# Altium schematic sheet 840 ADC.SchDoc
size 566 x 398 mm; Organization: Toradex Solutions Inc.; Address1: 6415 Northwest Drive; Address2: Mississauga, ON, L4V 1X1; Address3: Canada
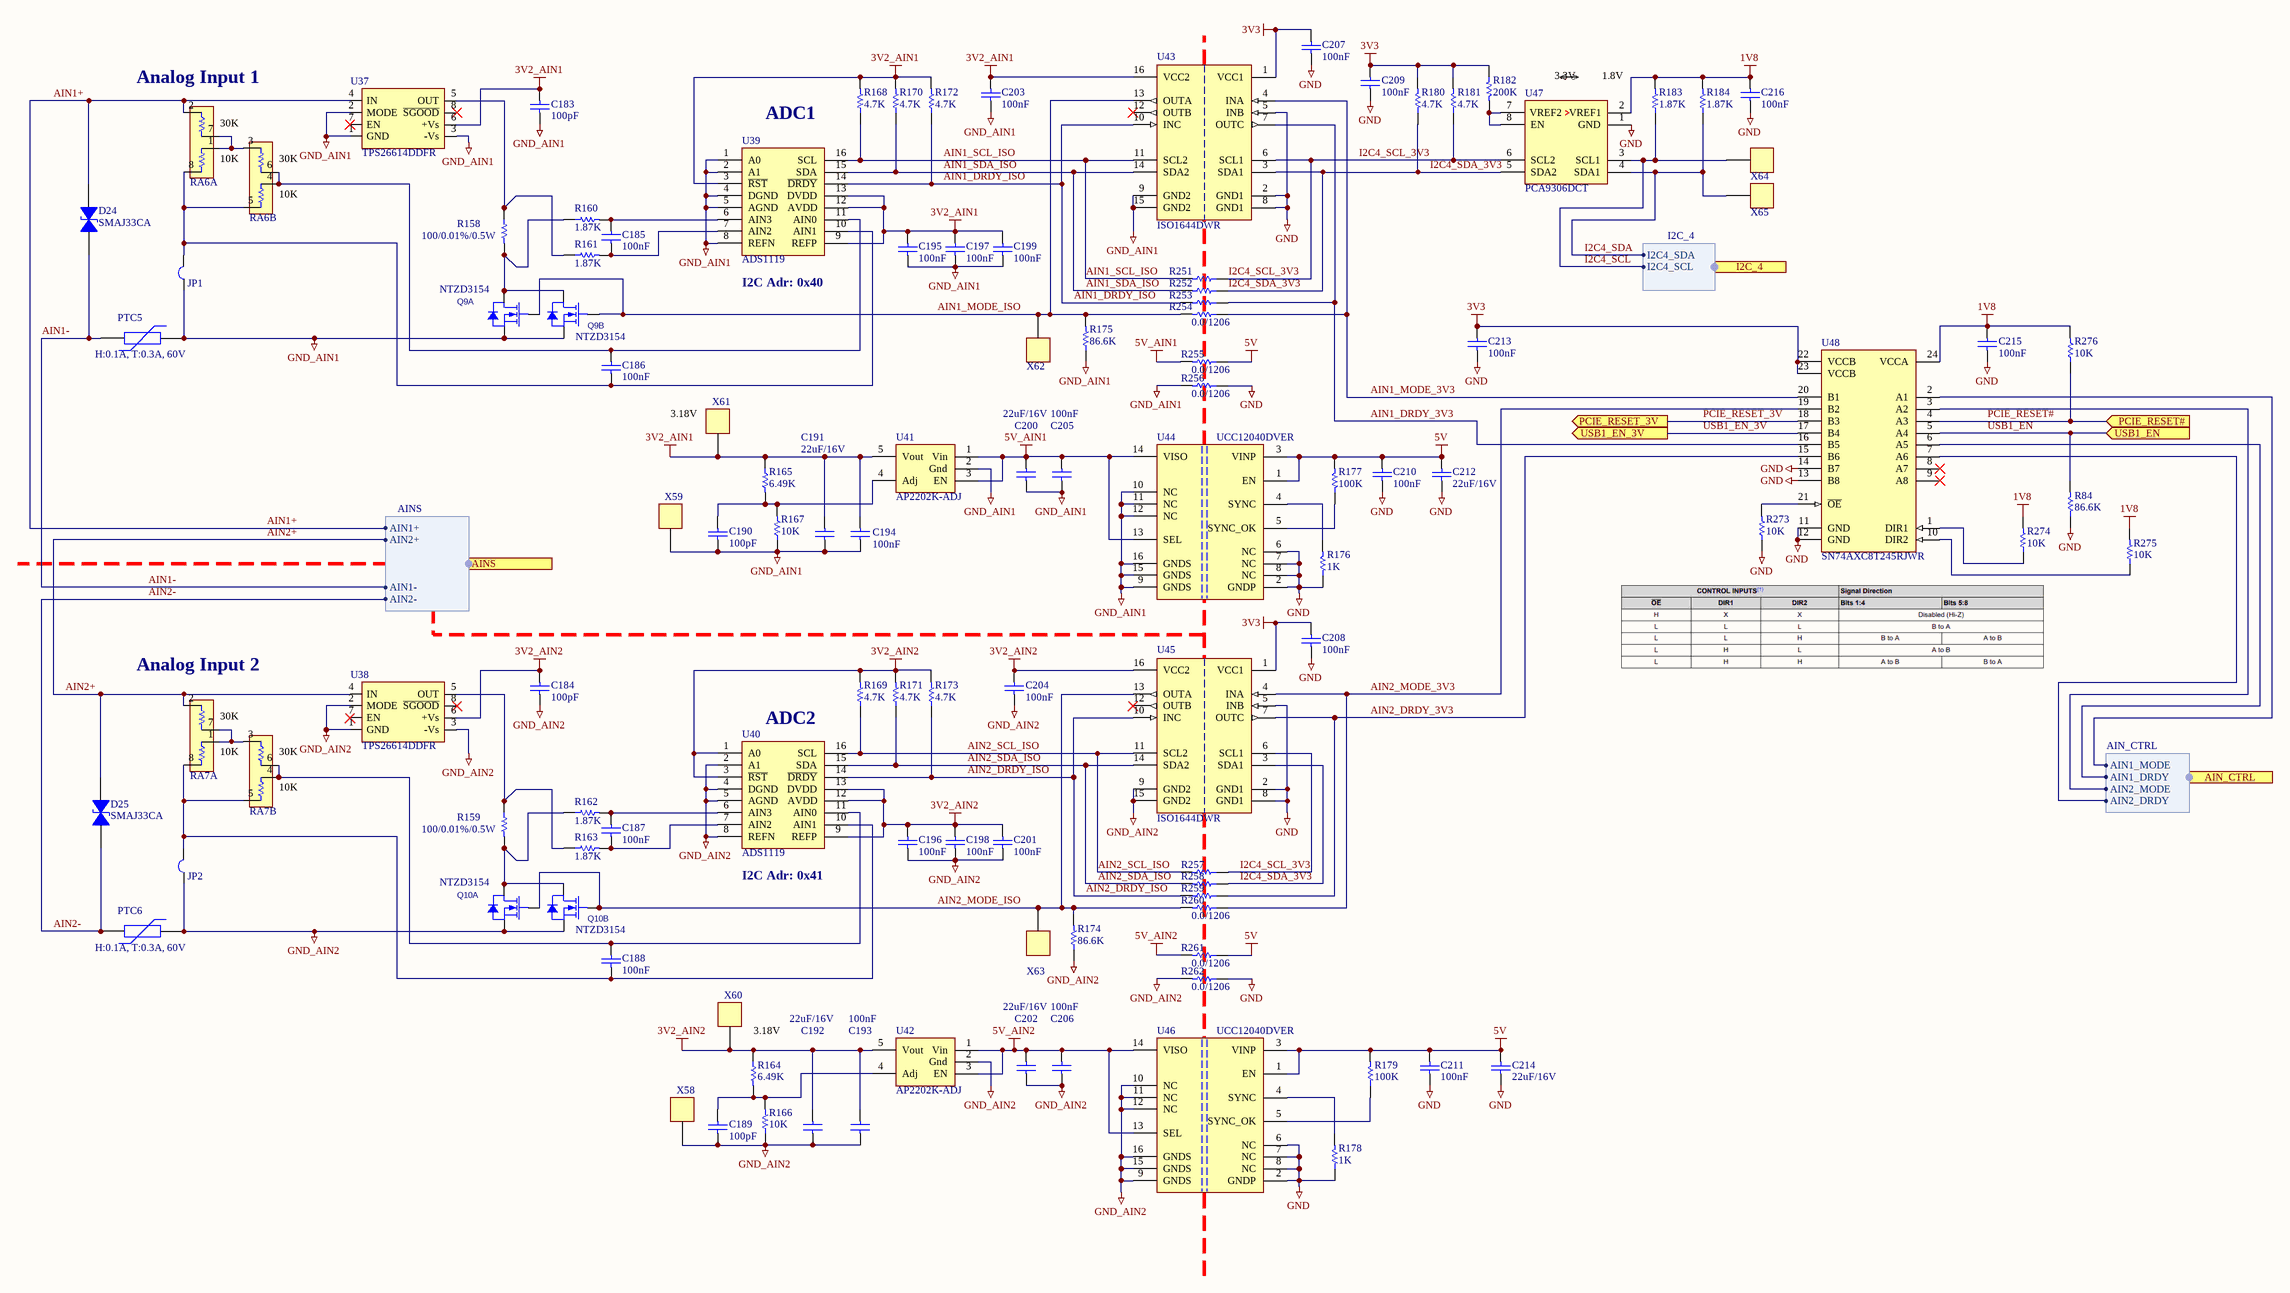
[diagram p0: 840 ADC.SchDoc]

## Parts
C183  value 100pF  [C0402_CAPC1005L]  (hidden comment: 1602-Cap-0402-100pF)
C184  value 100pF  [C0402_CAPC1005L]  (hidden comment: 1602-Cap-0402-100pF)
C185  100nF  [C0402_CAPC1005L]
C186  100nF  [C0402_CAPC1005L]
C187  100nF  [C0402_CAPC1005L]
C188  100nF  [C0402_CAPC1005L]
C189  value 100pF  [C0402_CAPC1005L]  (hidden comment: 1602-Cap-0402-100pF)
C190  value 100pF  [C0402_CAPC1005L]  (hidden comment: 1602-Cap-0402-100pF)
C191  value 22uF/16V  [C/0805]  (hidden comment: 1314-Cap-0805-22uF/16V)
C192  value 22uF/16V  [C/0805]  (hidden comment: 1314-Cap-0805-22uF/16V)
C193  100nF  [C0402_CAPC1005L]
C194  100nF  [C0402_CAPC1005L]
C195  100nF  [C0402_CAPC1005L]
C196  100nF  [C0402_CAPC1005L]
C197  100nF  [C0402_CAPC1005L]
C198  100nF  [C0402_CAPC1005L]
C199  100nF  [C0402_CAPC1005L]
C200  value 22uF/16V  [C/0805]  (hidden comment: 1314-Cap-0805-22uF/16V)
C201  100nF  [C0402_CAPC1005L]
C202  value 22uF/16V  [C/0805]  (hidden comment: 1314-Cap-0805-22uF/16V)
C203  100nF  [C0402_CAPC1005L]
C204  100nF  [C0402_CAPC1005L]
C205  100nF  [C0402_CAPC1005L]
C206  100nF  [C0402_CAPC1005L]
C207  100nF  [C0402_CAPC1005L]
C208  100nF  [C0402_CAPC1005L]
C209  100nF  [C0402_CAPC1005L]
C210  100nF  [C0402_CAPC1005L]
C211  100nF  [C0402_CAPC1005L]
C212  value 22uF/16V  [C/0805]  (hidden comment: 1314-Cap-0805-22uF/16V)
C213  100nF  [C0402_CAPC1005L]
C214  value 22uF/16V  [C/0805]  (hidden comment: 1314-Cap-0805-22uF/16V)
C215  100nF  [C0402_CAPC1005L]
C216  100nF  [C0402_CAPC1005L]
D24  SMAJ33CA  [SMAJ_TRANSIL]
D25  SMAJ33CA  [SMAJ_TRANSIL]
JP1  Short  [Short_040]  (value not drawn)
JP2  Short  [Short_040]  (value not drawn)
PTC5  H:0.1A, T:0.3A, 60V  [PTC_1812]
PTC6  H:0.1A, T:0.3A, 60V  [PTC_1812]
Q9  NTZD3154  [SOT563]  (parts A,B of 2)
Q10  NTZD3154  [SOT563]  (parts A,B of 2)
R84  value 86.6K  [R0402_RESC1005L]  (hidden comment: 1539-Res-0402-86.6k)
R158  value 100/0.01%/0.5W  [R/1206]  (hidden comment: 1192-Res-1206-100ohm-0.01%-0.5W)
R159  value 100/0.01%/0.5W  [R/1206]  (hidden comment: 1192-Res-1206-100ohm-0.01%-0.5W)
R160  value 1.87K  [R0402_RESC1005L]  (hidden comment: 1536-Res-0402-1.87K)
R161  value 1.87K  [R0402_RESC1005L]  (hidden comment: 1536-Res-0402-1.87K)
R162  value 1.87K  [R0402_RESC1005L]  (hidden comment: 1536-Res-0402-1.87K)
R163  value 1.87K  [R0402_RESC1005L]  (hidden comment: 1536-Res-0402-1.87K)
R164  value 6.49K  [R0402_RESC1005L]  (hidden comment: 1018-Res-0402-6.49K)
R165  value 6.49K  [R0402_RESC1005L]  (hidden comment: 1018-Res-0402-6.49K)
R166  value 10K  [R0402_RESC1005L]  (hidden comment: 1572-Res-0402-10K)
R167  value 10K  [R0402_RESC1005L]  (hidden comment: 1572-Res-0402-10K)
R168  value 4.7K  [R0402_RESC1005L]  (hidden comment: 2233-Res-0402-4.7K)
R169  value 4.7K  [R0402_RESC1005L]  (hidden comment: 2233-Res-0402-4.7K)
R170  value 4.7K  [R0402_RESC1005L]  (hidden comment: 2233-Res-0402-4.7K)
R171  value 4.7K  [R0402_RESC1005L]  (hidden comment: 2233-Res-0402-4.7K)
R172  value 4.7K  [R0402_RESC1005L]  (hidden comment: 2233-Res-0402-4.7K)
R173  value 4.7K  [R0402_RESC1005L]  (hidden comment: 2233-Res-0402-4.7K)
R174  value 86.6K  [R0402_RESC1005L]  (hidden comment: 1539-Res-0402-86.6k)
R175  value 86.6K  [R0402_RESC1005L]  (hidden comment: 1539-Res-0402-86.6k)
R176  value 1K  [R0402_RESC1005L]  (hidden comment: 1650-Res-0402-1K)
R177  value 100K  [R0402_RESC1005L]  (hidden comment: 1977-Res-0402-100K)
R178  value 1K  [R0402_RESC1005L]  (hidden comment: 1650-Res-0402-1K)
R179  value 100K  [R0402_RESC1005L]  (hidden comment: 1977-Res-0402-100K)
R180  value 4.7K  [R0402_RESC1005L]  (hidden comment: 2233-Res-0402-4.7K)
R181  value 4.7K  [R0402_RESC1005L]  (hidden comment: 2233-Res-0402-4.7K)
R182  value 200K  [R/0603]  (hidden comment: 1367-Res-0603-200K)
R183  value 1.87K  [R0402_RESC1005L]  (hidden comment: 1536-Res-0402-1.87K)
R184  value 1.87K  [R0402_RESC1005L]  (hidden comment: 1536-Res-0402-1.87K)
R251  0038-Res-1206-0.0ohm  [R/1206]  (value not drawn)
R252  0038-Res-1206-0.0ohm  [R/1206]  (value not drawn)
R253  0038-Res-1206-0.0ohm  [R/1206]  (value not drawn)
R254  value 0.0/1206  [R/1206]  (hidden comment: 0038-Res-1206-0.0ohm)
R255  value 0.0/1206  [R/1206]  (hidden comment: 0038-Res-1206-0.0ohm)
R256  value 0.0/1206  [R/1206]  (hidden comment: 0038-Res-1206-0.0ohm)
R257  0038-Res-1206-0.0ohm  [R/1206]  (value not drawn)
R258  0038-Res-1206-0.0ohm  [R/1206]  (value not drawn)
R259  0038-Res-1206-0.0ohm  [R/1206]  (value not drawn)
R260  value 0.0/1206  [R/1206]  (hidden comment: 0038-Res-1206-0.0ohm)
R261  value 0.0/1206  [R/1206]  (hidden comment: 0038-Res-1206-0.0ohm)
R262  value 0.0/1206  [R/1206]  (hidden comment: 0038-Res-1206-0.0ohm)
R273  value 10K  [R0402_RESC1005L]  (hidden comment: 1572-Res-0402-10K)
R274  value 10K  [R0402_RESC1005L]  (hidden comment: 1572-Res-0402-10K)
R275  value 10K  [R0402_RESC1005L]  (hidden comment: 1572-Res-0402-10K)
R276  value 10K  [R0402_RESC1005L]  (hidden comment: 1572-Res-0402-10K)
RA6  2066A-ResArr-1206-10kohm-30kohm  [RESNET-1206-4]  (value not drawn)  (parts A,B of 2)
RA7  2066A-ResArr-1206-10kohm-30kohm  [RESNET-1206-4]  (value not drawn)  (parts A,B of 2)
U37  TPS26614DDFR  [TSOT-23-8_TEX]
U38  TPS26614DDFR  [TSOT-23-8_TEX]
U39  ADS1119  [TSSOP16]
U40  ADS1119  [TSSOP16]
U41  AP2202K-ADJ  [SOT23-5]
U42  AP2202K-ADJ  [SOT23-5]
U43  ISO1644DWR  [SOIC-16]
U44  UCC12040DVER  [SOIC-16]
U45  ISO1644DWR  [SOIC-16]
U46  UCC12040DVER  [SOIC-16]
U47  PCA9306DCT  [TSSO3x5-G8/X.35]
U48  SN74AXC8T245RJWR  [UQFN-24]
X58  000-TestPoint  [TestPoint_1]  (value not drawn)
X59  000-TestPoint  [TestPoint_1]  (value not drawn)
X60  000-TestPoint  [TestPoint_1]  (value not drawn)
X61  000-TestPoint  [TestPoint_1]  (value not drawn)
X62  000-TestPoint  [TestPoint_1]  (value not drawn)
X63  000-TestPoint  [TestPoint_1]  (value not drawn)
X64  000-TestPoint  [TestPoint_1]  (value not drawn)
X65  000-TestPoint  [TestPoint_1]  (value not drawn)

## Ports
AIN_CTRL (harness AIN_CTRL), AINS (harness AINS), I2C_4 (harness I2C_4), PCIE_RESET# (in), PCIE_RESET_3V (out), USB1_EN (in), USB1_EN_3V (out)

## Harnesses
I2C_4: I2C4_SDA, I2C4_SCL
AIN_CTRL: AIN1_MODE, AIN2_MODE, AIN1_DRDY, AIN2_DRDY
AINS: AIN1+, AIN1-, AIN2+, AIN2-

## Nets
1V8: C215.2 C216.2 R183.2 R184.2 R274.2 R275.2 R276.2 U47.2(VREF1) U48.24(VCCA)
3V2_AIN1: C183.1 C191.2 C194.1 C195.2 C197.2 C199.2 C203.2 R165.1 R168.2 R170.2 R172.2 U37.6(+Vs) U39.3(~{RST}) U39.9(REFP) U39.12(AVDD) U39.13(DVDD) U41.5(Vout) U43.16(VCC2) X61.1
3V2_AIN2: C184.1 C192.2 C193.1 C196.2 C198.2 C201.2 C204.2 R164.1 R169.2 R171.2 R173.2 U38.6(+Vs) U40.1(A0) U40.3(~{RST}) U40.9(REFP) U40.12(AVDD) U40.13(DVDD) U42.5(Vout) U45.16(VCC2) X60.1
3V3: C207.2 C208.2 C209.2 C213.2 R180.2 R181.2 R182.1 U43.1(VCC1) U45.1(VCC1) U48.22(VCCB) U48.23(VCCB)
5V: C210.1 C211.1 C212.2 C214.2 R177.2 R179.2 R255.1 R261.1 U44.1(EN) U44.3(VINP) U46.1(EN) U46.3(VINP)
5V_AIN1: C200.2 C205.1 R255.2 U41.1(Vin) U41.3(EN) U44.13(SEL) U44.14(VISO)
5V_AIN2: C202.2 C206.1 R261.2 U42.1(Vin) U42.3(EN) U46.13(SEL) U46.14(VISO)
GND: C207.1 C208.1 C209.1 C210.2 C211.2 C212.1 C213.1 C214.1 C215.1 C216.1 R84.1 R176.1 R178.1 R256.1 R262.1 R273.1 U43.2(GND1) U43.5(INB) U43.8(GND1) U44.2(GNDP) U44.6(NC) U44.7(NC) U44.8(NC) U45.2(GND1) U45.5(INB) U45.8(GND1) U46.2(GNDP) U46.6(NC) U46.7(NC) U46.8(NC) U47.1(GND) U48.11(GND) U48.12(GND) U48.13(B8) U48.14(B7)
GND_AIN1: C183.2 C190.1 C191.1 C194.2 C195.1 C197.1 C199.1 C200.1 C203.1 C205.2 JP1.1(C1) PTC5.2 Q9.1(S) Q9.4(S) R167.1 R175.1 R256.2 U37.1(GND) U37.2(MODE) U37.3(-Vs) U39.1(A0) U39.2(A1) U39.4(DGND) U39.5(AGND) U39.8(REFN) U41.2(Gnd) U43.9(GND2) U43.15(GND2) U44.9(GNDS) U44.10(NC) U44.11(NC) U44.12(NC) U44.15(GNDS) U44.16(GNDS) X59.1
GND_AIN2: C184.2 C189.1 C192.1 C193.2 C196.1 C198.1 C201.1 C202.1 C204.1 C206.2 JP2.1(C1) PTC6.2 Q10.1(S) Q10.4(S) R166.1 R174.1 R262.2 U38.1(GND) U38.2(MODE) U38.3(-Vs) U40.2(A1) U40.4(DGND) U40.5(AGND) U40.8(REFN) U42.2(Gnd) U45.9(GND2) U45.15(GND2) U46.9(GNDS) U46.10(NC) U46.11(NC) U46.12(NC) U46.15(GNDS) U46.16(GNDS) X58.1
AIN1+: D24.1 RA6.2 U37.4(IN) ; port AINS.AIN1+
AIN1-: D24.2 PTC5.1 ; port AINS.AIN1-
AIN1_DRDY_3V3: R253.1 U43.7(OUTC) U48.16(B5)
AIN1_DRDY_ISO: R172.1 R253.2 U39.14(~{DRDY}) U43.10(INC)
AIN1_MODE_3V3: R254.1 U43.4(INA) U48.20(B1)
AIN1_MODE_ISO: Q9.2(G) Q9.5(G) R175.2 R254.2 U43.13(OUTA) X62.1
AIN1_SCL_ISO: R168.1 R251.2 U39.16(SCL) U43.11(SCL2)
AIN1_SDA_ISO: R170.1 R252.2 U39.15(SDA) U43.14(SDA2)
AIN2+: D25.1 RA7.2 U38.4(IN) ; port AINS.AIN2+
AIN2-: D25.2 PTC6.1 ; port AINS.AIN2-
AIN2_DRDY_3V3: R259.1 U45.7(OUTC) U48.15(B6)
AIN2_DRDY_ISO: R173.1 R259.2 U40.14(~{DRDY}) U45.10(INC)
AIN2_MODE_3V3: R260.1 U45.4(INA) U48.19(B2)
AIN2_MODE_ISO: Q10.2(G) Q10.5(G) R174.2 R260.2 U45.13(OUTA) X63.1
AIN2_SCL_ISO: R169.1 R257.2 U40.16(SCL) U45.11(SCL2)
AIN2_SDA_ISO: R171.1 R258.2 U40.15(SDA) U45.14(SDA2)
I2C4_SCL: R183.1 U47.3(SCL1) X64.1 ; port I2C_4.I2C4_SCL
I2C4_SCL_3V3: R181.1 R251.1 R257.1 U43.6(SCL1) U45.6(SCL1) U47.6(SCL2)
I2C4_SDA: R184.1 U47.4(SDA1) X65.1 ; port I2C_4.I2C4_SDA
I2C4_SDA_3V3: R180.1 R252.1 R258.1 U43.3(SDA1) U45.3(SDA1) U47.5(SDA2)
PCIE_RESET#: R276.1 U48.4(A3) ; port PCIE_RESET#
PCIE_RESET_3V: U48.18(B3) ; port PCIE_RESET_3V
USB1_EN: R84.2 U48.5(A4) ; port USB1_EN
USB1_EN_3V: U48.17(B4) ; port USB1_EN_3V
NetC185_1: C185.1 R161.2 U39.7(AIN2)
NetC185_2: C185.2 R160.2 U39.6(AIN3)
NetC186_1: C186.1 JP1.2(C2) RA6.5 RA6.8 U39.10(AIN1)
NetC186_2: C186.2 RA6.4 RA6.6 U39.11(AIN0)
NetC187_1: C187.1 R163.2 U40.7(AIN2)
NetC187_2: C187.2 R162.2 U40.6(AIN3)
NetC188_1: C188.1 JP2.2(C2) RA7.5 RA7.8 U40.10(AIN1)
NetC188_2: C188.2 RA7.4 RA7.6 U40.11(AIN0)
NetC189_2: C189.2 R164.2 R166.2 U42.4(Adj)
NetC190_2: C190.2 R165.2 R167.2 U41.4(Adj)
NetQ9_3: Q9.3(D) Q9.6(D) R158.2 R160.1
NetQ10_3: Q10.3(D) Q10.6(D) R159.2 R162.1
NetR158_1: R158.1 R161.1 U37.5(OUT)
NetR159_1: R159.1 R163.1 U38.5(OUT)
NetR176_2: R176.2 U44.4(SYNC)
NetR177_1: R177.1 U44.5(SYNC_OK)
NetR178_2: R178.2 U46.4(SYNC)
NetR179_1: R179.1 U46.5(SYNC_OK)
NetR182_2: R182.2 U47.7(VREF2) U47.8(EN)
NetR273_2: R273.2 U48.21(~{OE})
NetR274_1: R274.1 U48.1(DIR1)
NetR275_1: R275.1 U48.10(DIR2)
NetRA6_1: RA6.1 RA6.3 RA6.7
NetRA7_1: RA7.1 RA7.3 RA7.7
NetU48_2: U48.2(A1) ; port AIN_CTRL.AIN1_MODE
NetU48_3: U48.3(A2) ; port AIN_CTRL.AIN2_MODE
NetU48_6: U48.6(A5) ; port AIN_CTRL.AIN1_DRDY
NetU48_7: U48.7(A6) ; port AIN_CTRL.AIN2_DRDY

Not connected (* = marked no-connect by the designer): U37 7(EN)* 8(~{SGOOD})*; U38 7(EN)* 8(~{SGOOD})*; U43 12(OUTB)*; U45 12(OUTB)*; U48 8(A7)* 9(A8)*

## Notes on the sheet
- (near RA6) Analog Input 1
- 3.3V
- (near U47) 1.8V
- ADC1
- (near U39) I2C Adr: 0x40
- (near X61) 3.18V
- (near RA7) Analog Input 2
- (near U40) ADC2
- (near U40) I2C Adr: 0x41
- 3.18V

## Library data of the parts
C183 C184 C189 C190 = 1602-Cap-0402-100pF: (-55 to 125 Degc AEC) CAP CER 100PF 50V 5% NPO 0402; Mfr: Murata; MfrNo: GCM1555C1H101JA16D; PN: 1602; Alt: UMK105CH101JVHF,GRT1555C1H101JA02D,GRT1555C1H101JA02J,CL05C101JB51PNC
C185-C188 C193-C199 C201 C203-C211 C213 C215 C216 = 1566-Cap-0402-100nF/50V: (-55 to 125 DegC AEC) Cap Ceramic 0.1uF 50V X7R 10% 0402; MfrNo: GRT155R71H104KE01D; Mfr: Murata; Alt: CL05B104KB54PNC,GCM155R71H104ME02D,GCM155R71H104KE02D,GCM155R71H104KE02J; PN: 1566
C191 C192 C200 C202 C212 C214 = 1314-Cap-0805-22uF/16V: (-55 to 85 DegC) CAP CER 22uF 16V X5R 0805; MfrNo: CL21A226MOQNNNE; Mfr: Samsung; PN: 1314; Alt: CL21A226MOCLRNC,CL21A226KOQNNNG,GRM21BR61C226ME44L,EMK212BBJ226MG-T
D24 D25 = 0581-SMAJ33CA: (-55 to 150 DegC) TVS DIODE 33VWM Vbrm:36.7V Vcl:53.3V 400W SMA; MfrNo: SMAJ33CA-E3/5A; Mfr: Vishay Semiconductor Diodes Division; PN: 581; Desc: (-55 to 150 DegC) TVS DIODE 33VWM Vbrm:36.7V Vstd:53.3VC SMA; Alt: SMAJ33CA-E3/61GICT-ND; Alt2: SMAJ33CABCT-ND; DR: SMAJ33CA-E3/5AGIDKR-ND; DR2: 625-SMAJ33CA-E3/5A
JP1 JP2 = 000-Jumper-Short: Jumper Wire
PTC5 PTC6 = 1423-PTC-0.1A-60V-1812: (-40 to 85 DegC) PTC Ih:0.1A, It:0.3A, 60V, 1812, 1.6-15ohm; MfrNo: 0ZCG0010FF2C; Mfr: Bel; PN: 1423; Alt: MPTS1812L010R,MPTS1812L010,1812L010/60DR,PTSA181260V010,MF-MSMF010-2,PFMF.010.2,MINISMDC010F-2,MINIASMDC010F-2
Q9 Q10 = 1146-NTZD3154NT1G: (-55 to 150 DegC) MOSFET 2N-CH (dual) 20V 0.54A SOT-563 1.6x1.6mm Vth:1V Ron typ:400m@4.5V, 500m@2.5V, 700m@1.8V; Mfr: ON Semiconductor; PN: 1146; Alt: NTZD3154NT5G,PMDT290UNE,115
R84 R174 R175 = 1539-Res-0402-86.6k: (-55 to 155 DegC AEC) RES 86.6K OHM 1% 1/16W 100ppm 0402; Mfr: Stackpole Electronics; MfrNo: RMCF0402FT86K6; Alt: AC0402FR-0786K6L,RK73H1ETTP8662F,ERJ-2RKF8662X; PN: 1539
R158 R159 = 1192-Res-1206-100ohm-0.01%-0.5W: RES SMD 100 OHM 0.01% 0.5W 1206 5ppm; Mfr: Stackpole Electronics; MfrNo: RNCF1206TKY100R; PN: 1192; Note: similar at lower prec: PN1432, TNPU1206100RBZEN00,TNPU1206100RAZEN00
R160-R163 R183 R184 = 1536-Res-0402-1.87K: (-55 to 155 DegC AEC) RES 1.87K OHM 1% 1/16W 100ppm 0402; MfrNo: RMCF0402FT1K87; Mfr: Stackpole Electronics; Alt: AC0402FR-071K87L,RK73H1ETTP1871F,ERJ-2RKF1871X; PN: 1536
R164 R165 = 1018-Res-0402-6.49K: (-55 to 155 DegC) RES SMD 6.49K OHM 1% 1/16W 0402; Mfr: Yageo; MfrNo: RC0402FR-076K49L; Alt: RMCF0402FT6K49,RC1005F6491CS,ERJ-2RKF6491X; PN: 1018
R166 R167 R273-R276 = 1572-Res-0402-10K: (-55 to 155 DegC AEC) RES 10K OHM 1% 1/16W 100ppm 0402; Mfr: Stackpole Electronics; MfrNo: RMCF0402FT10K0; Alt: AC0402FR-0710KL,AC0402FR-1310KL,CRGCQ0402F10K; PN: 1572
R168-R173 R180 R181 = 2233-Res-0402-4.7K: (-55 to 155 DegC) RES 4.70K OHM 1/16W 1% 0402 100ppm; MfrNo: RC0402FR-074K7L; Mfr: Yageo; PN: 2233
R176 R178 = 1650-Res-0402-1K: (-55 to 155 DegC AEC) RES 1K OHM 1% 1/16W 100ppm 0402; Mfr: TE Connectivity; MfrNo: CRGCQ0402F1K0; PN: 1650; Alt: CR0402AFX-1001GLF,AC0402FR-131KL,AC0402FR-071KL
R177 R179 = 1977-Res-0402-100K: (-55 to 155 DegC) RES 100K OHM 1/16W 1% 0402 SMD; Mfr: Yageo; MfrNo: RC0402FR-07100KL; PN: 1977
R182 = 1367-Res-0603-200K: (-55 to 155 DegC) RES SMD 200K 1% 1/10W 0603 100ppm; Mfr: Stackpole Electronics; MfrNo: RMCF0603FT200K; Alt: CR0603-FX-2003ELF,RC0603FR-07200KL,RK73H1JTTD2003F; PN: 1367
R251-R262 = 0038-Res-1206-0.0ohm: (-55 to 155 DegC) RES 0.0 OHM 1/4W JUMPER 1206; Mfr: TE; MfrNo: 1623693-1; PN: 38; Alt: 311-0.0ERCT-ND; Alt2: RMCF1206ZT0R00CT-ND
RA6 RA7 = 2066A-ResArr-1206-10kohm-30kohm: (-55 to 125 DegC) RES ARRAY 4 RES 10 kOHM 30 kOHM 1206; Mfr: Vishay Beyschlag; MfrNo: ACASA1002S3002P100; PN: 2066
U37 U38 = 1870-TPS26614: (-40 to 155 DegC) IC Current Loop Protector 50V TSOT-23-8; Mfr: Texas Instruments; PN: 1870
U39 U40 = 1414-ADS1119: (-40 to 125 DegC) IC ADC 16BIT 4ch 1000SPS 16-TSSOP I2C Adr 0x40-0x4F IntRef SigmaDelta; Mfr: Texas Instruments; MfrNo: ADS1119IPWR; PN: 1414; Alt: ADS1119IPW, ADS1119IPWT
U41 U42 = 0619-AP2202K-ADJ: (-40 to 125 DegC) IC REG LDO ADJ 0.15A SOT23-5 13.2V; Mfr: Diodes Incorporated; MfrNo: AP2202K-ADJTRG1; PN: 619; DR: AP2202K-ADJTRG1DIDKR-ND; DR2: 621-AP2202K-ADJTRG1
U43 U45 = 2064-ISO1644DWR: (-40 to 125 DegC) DGTL ISO 5KV 5CH I2C 16SOIC; Mfr: Texas Instruments; PN: 2064
U44 U46 = 2065-UCC12040DVER: (-40 to 125 DegC) IC Isolated DC DC Converter-Output 3.3V, 5V 140mA, 4.5V-5.5V Input; Mfr: Texas Instruments; PN: 2065
U47 = 0972-PCA9306DCT: (-40 to 85 DegC) IC TRANSLTR BIDIRECTIONAL I2C SM8; MfrNo: PCA9306DCTR; Mfr: Texas Instruments; PN: 972
U48 = 2540-SN74AXC8T245RJWR: (-40 to 125 DegC) IC TRANSLATION TXRX 0.65-3.6V 24UQFN; Mfr: Texas Instruments; PN: 2540
X58-X65 = 000-TestPoint: Note: this is PCB footprint only, no parts to buy or assemble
